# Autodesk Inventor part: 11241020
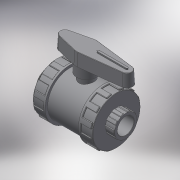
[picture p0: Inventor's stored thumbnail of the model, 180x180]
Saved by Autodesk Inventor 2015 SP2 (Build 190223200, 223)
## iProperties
Created: 2017-11
Part Number: 11241020
Material: Generic
Description: PLASSON BI STOP VALVE THR PVC 2"
Document SubType Name: Modeling
Designer: KIM
Density: 1 g/cm^3
Appearance: Default
Author: KIM
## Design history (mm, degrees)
derived "112410 - 112710.ipt"
feature "Solid1::112410 - 112710.ipt"
tag "TaggingFeature1"
body "Solid1"
other parameters: "d0" = 169, "d1" = 56.656, "d2" = 118, "d3" = 26, "d4" = 45.3248, "d5" = 18.2, "d7" = 79.3184, "d8" = 106.2, "d13" = 1.69968, "d23" = 26, "d24" = 113.28, "d25" = 1.13312, "d26" = 1.69968, "d27" = 17.7, "d28" = 8.85, "d29" = 19.5, "d30" = 0, "d35" = 1.69968, "d39" = 59, "d45" = 360 deg, "d47" = 1.13312, "d50" = 64.9, "d51" = 35.4, "d53" = 0, "d55" = 11.3312, "d56" = 5.6656, "d57" = 18.2, "d58" = 0, "d59" = 1.69968, "d61" = 360 deg, "d63" = 47.2, "d64" = 106, "d66" = 129, "d68" = 23.6, "d69" = 38.7, "d70" = 26.5, "d71" = 3 deg, "d73" = 2.36, "d74" = 51.6, "d75" = 3.18, "d76" = 0, "d77" = 1.13312, "G_" = 56.656, "l_" = 26, "H_" = 169, "K_" = 118, "F_" = 106, "J_" = 129, "d67" = 47.2, "d72" = 11.8
